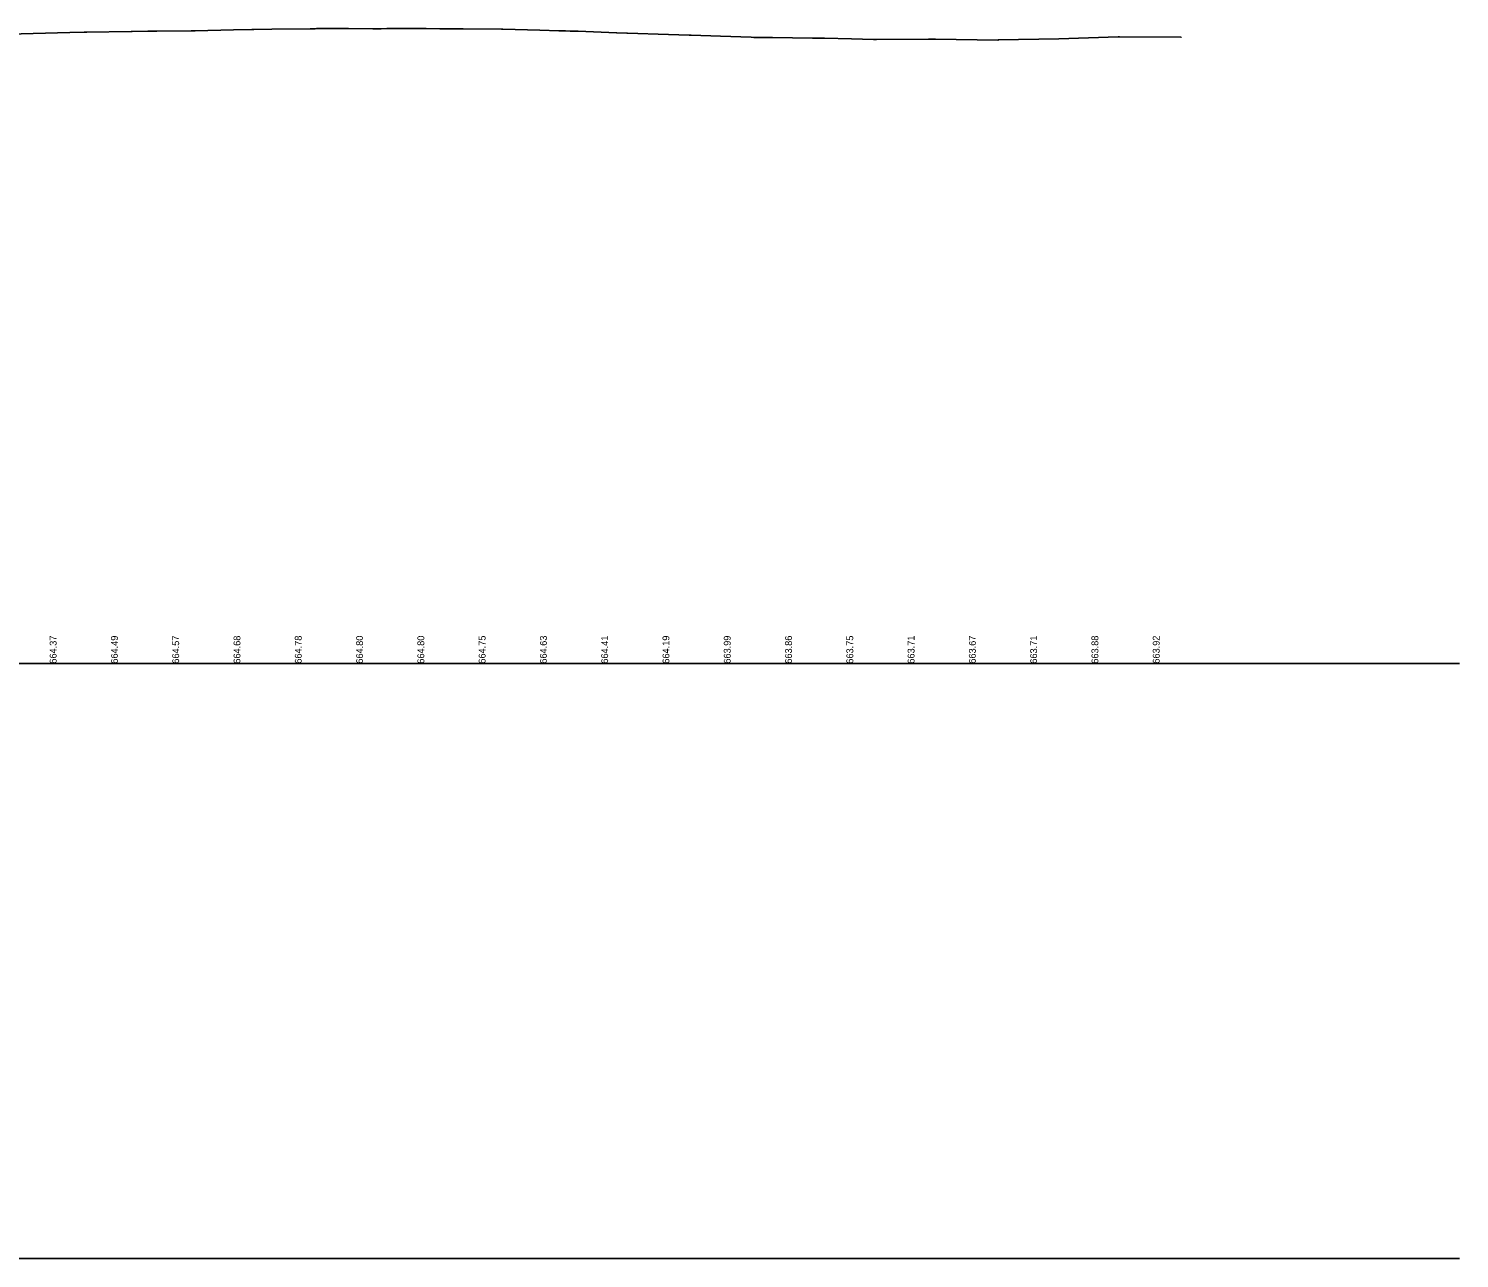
# Model space of a CAD drawing. Extents: x 2283072 to 2287933, y 586198 to 587702.
# Drawn here: x 2287349 to 2287933, y 586198 to 586700 of the extents above; entities that cross this region are included whole.
import ezdxf

# ---------------------------------------------------------------- set-up
doc = ezdxf.new("R2010")
doc.units = 0
for name, color, linetype in [('DT_X_Terrain_Ground_Line', 7, 'Continuous'), ('DT_X_Triangles', 7, 'Continuous'), ('RD_X_GR_Lt', 7, 'Continuous'), ('SV_P_Control_Cells_Set', 7, 'Continuous')]:
    doc.layers.add(name, color=color, linetype=linetype)

msp = doc.modelspace()

# ---------------------------------------------------------------- linework, layer by layer
at = {"layer": 'DT_X_Terrain_Ground_Line'}
msp.add_line((2286710.71, 586440.9), (2287932.99, 586440.9), dxfattribs=at)
at = {"layer": 'DT_X_Triangles'}
msp.add_lwpolyline([(2287341.27, 586697.84), (2287366.16, 586698.52), (2287371.9, 586698.64), (2287373.07, 586698.67), (2287391.13, 586698.96), (2287391.5, 586698.96), (2287397.91, 586699.04), (2287401.6, 586699.07), (2287415.67, 586699.22), (2287416.09, 586699.23), (2287417.23, 586699.26), (2287432.86, 586699.57), (2287440.43, 586699.72), (2287441.14, 586699.76), (2287448.49, 586699.87), (2287464.12, 586700.06), (2287466.21, 586700.07), (2287466.72, 586700.09), (2287479.75, 586700.11), (2287489.69, 586700.07), (2287491.44, 586700.06), (2287491.46, 586700.06), (2287491.51, 586700.06), (2287493.1, 586700.08), (2287495.38, 586700.1), (2287511.01, 586700.11), (2287511.45, 586700.11), (2287517.13, 586700.04), (2287517.43, 586700.04), (2287517.9, 586700.06), (2287524.53, 586700.04), (2287526.64, 586700.03), (2287542.27, 586699.84), (2287542.8, 586699.83), (2287542.82, 586699.83), (2287557.9, 586699.49), (2287565.56, 586699.27), (2287568.17, 586699.2), (2287568.3, 586699.2), (2287570.28, 586699.13), (2287573.53, 586699.01), (2287589.16, 586698.42), (2287589.3, 586698.41), (2287593.32, 586698.24), (2287593.65, 586698.24), (2287610.38, 586697.69), (2287618.72, 586697.4), (2287619.61, 586697.39), (2287631.59, 586696.99), (2287644.09, 586696.56), (2287645.12, 586696.54), (2287652.81, 586696.45), (2287669.03, 586696.26), (2287669.55, 586696.25), (2287674.03, 586696.15), (2287684.97, 586695.9), (2287693.97, 586695.69), (2287694.13, 586695.69), (2287695.24, 586695.7), (2287716.46, 586695.79), (2287717.74, 586695.79), (2287719.26, 586695.8), (2287719.31, 586695.8), (2287744.64, 586695.46), (2287745.02, 586695.47), (2287769.64, 586695.88), (2287793.85, 586696.69), (2287794.34, 586696.7), (2287794.36, 586696.7), (2287819.38, 586696.55), (2287819.55, 586696.55), (2287819.55, 586696.55)], dxfattribs=at)
at = {"layer": 'SV_P_Control_Cells_Set'}
msp.add_line((2286710.71, 586198.14), (2287932.99, 586198.14), dxfattribs=at)

# ---------------------------------------------------------------- texts
at = {"layer": 'RD_X_GR_Lt'}
for s, p in [('664.37', (2287360.71, 586440.9)), ('664.49', (2287385.71, 586440.9)), ('664.57', (2287410.71, 586440.9)), ('664.68', (2287435.71, 586440.9)), ('664.78', (2287460.71, 586440.9)), ('664.80', (2287485.71, 586440.9)), ('664.80', (2287510.71, 586440.9)), ('664.75', (2287535.71, 586440.9)), ('664.63', (2287560.71, 586440.9)), ('664.41', (2287585.71, 586440.9)), ('664.19', (2287610.71, 586440.9)), ('663.99', (2287635.71, 586440.9)), ('663.86', (2287660.71, 586440.9)), ('663.75', (2287685.71, 586440.9)), ('663.71', (2287710.71, 586440.9)), ('663.67', (2287735.71, 586440.9)), ('663.71', (2287760.71, 586440.9)), ('663.88', (2287785.71, 586440.9)), ('663.92', (2287810.71, 586440.9))]:
    msp.add_text(s, height=2.8, rotation=90, dxfattribs=at).set_placement(p)

doc.saveas('drawing.dxf')
